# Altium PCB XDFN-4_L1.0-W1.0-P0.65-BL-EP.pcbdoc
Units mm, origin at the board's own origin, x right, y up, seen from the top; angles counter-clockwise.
Board outline 14.34 x 14.1 mm, 2 copper layers (Top Layer, Bottom Layer), stack 0 mm thick; 1 components, 0 nets, 5 pads, 0 vias.
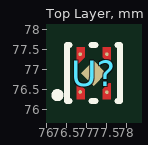
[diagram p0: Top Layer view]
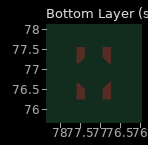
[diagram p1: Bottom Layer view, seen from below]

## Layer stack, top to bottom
Top Layer: signal copper (thickness not stored)
Bottom Layer: signal copper (thickness not stored)

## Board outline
84.186,69.85 69.85,69.85 69.85,83.95 84.186,83.95

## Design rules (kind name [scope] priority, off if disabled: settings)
PasteMaskExpansion "Paste Mask Expansion" [All] p1: expansion=0
SolderMaskExpansion "Solder Mask Expansion" [IsVia] p1: expansion=-25.4 istentingtop=TRUE
SolderMaskExpansion "Solder Mask Expansion" [All] p2: expansion=0.051 istentingtop=FALSE

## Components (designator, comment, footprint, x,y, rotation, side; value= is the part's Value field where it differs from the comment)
U? "" XDFN-4_L1.0-W1.0-P0.65-BL-EP 77.176,76.9 r0 top

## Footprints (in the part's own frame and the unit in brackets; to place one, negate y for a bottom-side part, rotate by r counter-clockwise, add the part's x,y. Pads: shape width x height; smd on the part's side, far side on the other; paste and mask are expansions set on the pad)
XDFN-4_L1.0-W1.0-P0.65-BL-EP [mm]
  round 0.09 smd: 1(-0.335,-0.47)
  round 0.092 smd: 2(0.333,-0.475) 3(0.333,0.475) 4(-0.333,0.475)
  rect 0.45x0.45 smd rot 45: 5(0,0)
  Top Layer region: 0.425,-0.65 0.225,-0.65 0.225,-0.4 0.375,-0.25 0.425,-0.25
  Top Layer region: -0.425,0.65 -0.225,0.65 -0.225,0.4 -0.375,0.25 -0.425,0.25
  Top Layer region: 0.425,0.65 0.225,0.65 0.225,0.4 0.375,0.25 0.425,0.25
  Top Layer region: -0.225,-0.4 -0.225,-0.65 -0.425,-0.65 -0.425,-0.2 -0.375,-0.25
  silkscreen extent -0.98,-0.7 0.66,0.7

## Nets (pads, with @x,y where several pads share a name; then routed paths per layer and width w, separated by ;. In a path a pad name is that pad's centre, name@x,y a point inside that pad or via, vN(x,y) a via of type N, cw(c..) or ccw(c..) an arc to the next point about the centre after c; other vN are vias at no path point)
pads on no net: U?.1 U?.2 U?.3 U?.4 U?.5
